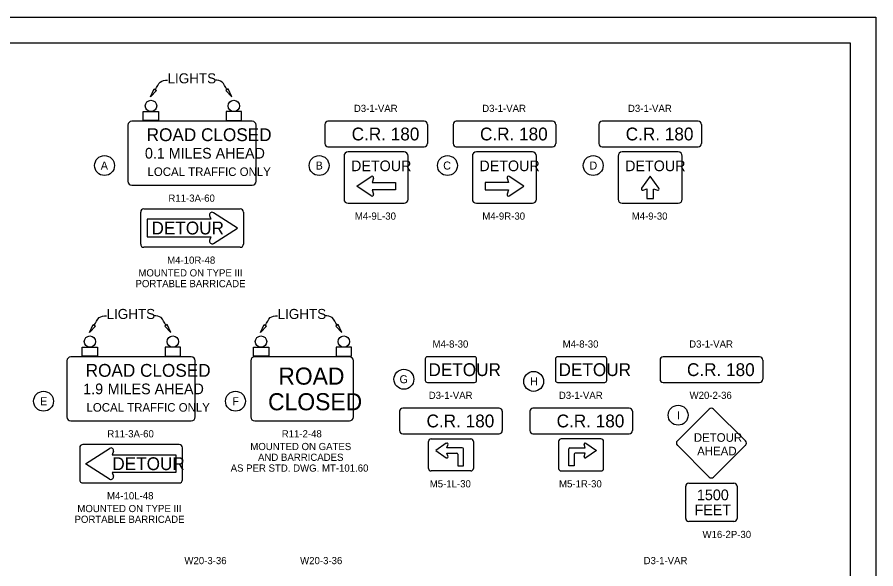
# Model space of a CAD drawing. Extents: x 1651.5 to 1685.5, y 1084.6 to 1106.6.
# Drawn here: x 1668.74 to 1685.46, y 1095.85 to 1106.6 of the extents above; entities that cross this region are included whole.
import ezdxf

# ---------------------------------------------------------------- set-up
doc = ezdxf.new("R2010")
doc.units = 0
for name, color, linetype in [('SC_Scratch1', 7, 'Continuous'), ('SH_Border', 7, 'Continuous'), ('SH_Text', 7, 'Continuous'), ('SN_P_Signs', 7, 'Continuous'), ('SN_P_Text', 7, 'Continuous')]:
    doc.layers.add(name, color=color, linetype=linetype)

msp = doc.modelspace()

# ---------------------------------------------------------------- linework, layer by layer
at = {"layer": 'SC_Scratch1'}
msp.add_lwpolyline([(1651.463, 1106.601), (1685.463, 1106.601), (1685.463, 1084.601), (1651.463, 1084.601)], close=True, dxfattribs=at)
at = {"layer": 'SH_Border'}
msp.add_lwpolyline([(1651.963, 1106.101), (1684.963, 1106.101), (1684.963, 1085.101), (1651.963, 1085.101)], close=True, dxfattribs=at)
at = {"layer": 'SH_Text'}
for centre in [(1670.438, 1103.708), (1674.618, 1103.708), (1677.118, 1103.708), (1679.958, 1103.708), (1676.27, 1099.542), (1678.797, 1099.5), (1669.25, 1099.114), (1672.989, 1099.114), (1681.612, 1098.841)]:
    msp.add_circle(centre, 0.194, dxfattribs=at)
at = {"layer": 'SN_P_Signs'}
for p, q in [((1675.353, 1103.307), (1675.634, 1103.497)), ((1678.603, 1103.307), (1678.322, 1103.497)), ((1681.068, 1103.503), (1680.9, 1103.264)), ((1681.236, 1103.264), (1681.068, 1103.503)), ((1675.677, 1103.465), (1675.65, 1103.38)), ((1675.65, 1103.38), (1676.103, 1103.38)), ((1676.103, 1103.38), (1676.103, 1103.234)), ((1678.306, 1103.38), (1677.853, 1103.38)), ((1677.853, 1103.38), (1677.853, 1103.234)), ((1678.279, 1103.465), (1678.306, 1103.38)), ((1675.634, 1103.116), (1675.353, 1103.307)), ((1676.103, 1103.234), (1675.65, 1103.234)), ((1675.65, 1103.234), (1675.677, 1103.149)), ((1677.853, 1103.234), (1678.306, 1103.234)), ((1678.306, 1103.234), (1678.279, 1103.149)), ((1678.322, 1103.116), (1678.603, 1103.307)), ((1680.928, 1103.227), (1681.005, 1103.251)), ((1681.005, 1103.251), (1681.005, 1103.25)), ((1681.005, 1103.25), (1681.005, 1103.066)), ((1681.131, 1103.251), (1681.208, 1103.227)), ((1681.005, 1103.066), (1681.131, 1103.066)), ((1672.507, 1102.661), (1671.268, 1102.661)), ((1671.268, 1102.661), (1671.268, 1102.318)), ((1672.485, 1102.731), (1672.507, 1102.661)), ((1673.028, 1102.489), (1672.559, 1102.788)), ((1672.559, 1102.191), (1673.028, 1102.489)), ((1671.268, 1102.318), (1672.507, 1102.318)), ((1672.507, 1102.318), (1672.485, 1102.248)), ((1676.749, 1097.804), (1676.749, 1098.329)), ((1676.799, 1098.379), (1677.574, 1098.379)), ((1677.624, 1098.329), (1677.624, 1097.804)), ((1679.284, 1098.329), (1679.284, 1097.804)), ((1680.109, 1098.379), (1679.334, 1098.379)), ((1680.159, 1097.804), (1680.159, 1098.329)), ((1670.069, 1097.896), (1670.537, 1098.194)), ((1670.612, 1098.137), (1670.59, 1098.068)), ((1677.094, 1098.293), (1676.89, 1098.153)), ((1676.89, 1098.153), (1677.094, 1098.013)), ((1677.109, 1098.208), (1677.13, 1098.278)), ((1677.406, 1098.208), (1677.109, 1098.208)), ((1677.406, 1098.208), (1677.406, 1098.208)), ((1677.429, 1097.856), (1677.429, 1098.184)), ((1679.48, 1097.856), (1679.48, 1098.184)), ((1679.503, 1098.208), (1679.8, 1098.208)), ((1679.503, 1098.208), (1679.503, 1098.208)), ((1679.8, 1098.208), (1679.779, 1098.278)), ((1679.815, 1098.293), (1680.019, 1098.153)), ((1680.019, 1098.153), (1679.815, 1098.013)), ((1670.59, 1098.068), (1671.829, 1098.068)), ((1671.829, 1098.068), (1671.829, 1097.724)), ((1677.13, 1098.028), (1677.109, 1098.098)), ((1677.109, 1098.098), (1677.304, 1098.098)), ((1677.32, 1098.083), (1677.32, 1097.856)), ((1679.589, 1098.083), (1679.589, 1097.856)), ((1679.8, 1098.098), (1679.605, 1098.098)), ((1679.779, 1098.028), (1679.8, 1098.098)), ((1670.537, 1097.597), (1670.069, 1097.896)), ((1677.32, 1097.856), (1677.429, 1097.856)), ((1677.32, 1097.856), (1677.429, 1097.856)), ((1679.589, 1097.856), (1679.48, 1097.856)), ((1671.829, 1097.724), (1670.59, 1097.724)), ((1670.59, 1097.724), (1670.612, 1097.654)), ((1677.574, 1097.754), (1676.799, 1097.754)), ((1679.334, 1097.754), (1680.109, 1097.754))]:
    msp.add_line(p, q, dxfattribs=at)
for points in [[(1671.451, 1105.172), (1671.333, 1105.049), (1671.404, 1105.203)], [(1672.8, 1105.172), (1672.918, 1105.049), (1672.847, 1105.203)], [(1671.193, 1104.587), (1671.193, 1104.759), (1671.492, 1104.759), (1671.492, 1104.587)], [(1673.105, 1104.587), (1673.105, 1104.759), (1672.806, 1104.759), (1672.806, 1104.587)], [(1670.263, 1100.578), (1670.145, 1100.455), (1670.216, 1100.61)], [(1671.612, 1100.578), (1671.729, 1100.455), (1671.658, 1100.61)], [(1673.594, 1100.578), (1673.477, 1100.455), (1673.548, 1100.61)], [(1674.944, 1100.578), (1675.061, 1100.455), (1674.99, 1100.61)], [(1670.005, 1099.993), (1670.005, 1100.165), (1670.304, 1100.165), (1670.304, 1099.993)], [(1671.917, 1099.993), (1671.917, 1100.165), (1671.618, 1100.165), (1671.618, 1099.993)], [(1673.337, 1099.993), (1673.337, 1100.165), (1673.636, 1100.165), (1673.636, 1099.993)], [(1675.249, 1099.993), (1675.249, 1100.165), (1674.95, 1100.165), (1674.95, 1099.993)]]:
    msp.add_lwpolyline(points, close=True, dxfattribs=at)
for points in [[(1670.893, 1104.495), (1670.893, 1103.401)], [(1673.314, 1104.573), (1670.971, 1104.573)], [(1673.393, 1103.401), (1673.393, 1104.495)], [(1674.728, 1104.511), (1674.728, 1104.136)], [(1676.666, 1104.573), (1674.791, 1104.573)], [(1676.728, 1104.511), (1676.728, 1104.136)], [(1677.228, 1104.511), (1677.228, 1104.136)], [(1679.166, 1104.573), (1677.291, 1104.573)], [(1679.228, 1104.511), (1679.228, 1104.136)], [(1680.068, 1104.511), (1680.068, 1104.136)], [(1682.005, 1104.573), (1680.13, 1104.573)], [(1682.068, 1104.511), (1682.068, 1104.136)], [(1674.791, 1104.073), (1676.666, 1104.073)], [(1677.291, 1104.073), (1679.166, 1104.073)], [(1680.13, 1104.073), (1682.005, 1104.073)], [(1675.103, 1103.893), (1675.103, 1103.053)], [(1676.273, 1103.973), (1675.183, 1103.973)], [(1676.353, 1103.053), (1676.353, 1103.893)], [(1677.603, 1103.893), (1677.603, 1103.053)], [(1678.773, 1103.973), (1677.683, 1103.973)], [(1678.853, 1103.053), (1678.853, 1103.893)], [(1680.443, 1103.893), (1680.443, 1103.053)], [(1681.613, 1103.973), (1680.523, 1103.973)], [(1681.693, 1103.053), (1681.693, 1103.893)], [(1670.971, 1103.323), (1673.314, 1103.323)], [(1681.131, 1103.066), (1681.131, 1103.25)], [(1671.205, 1102.864), (1673.08, 1102.864)], [(1675.183, 1102.973), (1676.273, 1102.973)], [(1677.683, 1102.973), (1678.773, 1102.973)], [(1680.523, 1102.973), (1681.613, 1102.973)], [(1671.143, 1102.177), (1671.143, 1102.802)], [(1673.143, 1102.802), (1673.143, 1102.177)], [(1673.08, 1102.114), (1671.205, 1102.114)], [(1672.126, 1099.979), (1669.782, 1099.979)], [(1675.208, 1099.979), (1673.364, 1099.979)], [(1677.647, 1099.979), (1676.727, 1099.979)], [(1680.182, 1099.979), (1679.262, 1099.979)], [(1683.197, 1099.979), (1681.322, 1099.979)], [(1669.704, 1099.901), (1669.704, 1098.808)], [(1672.204, 1098.808), (1672.204, 1099.901)], [(1673.286, 1099.901), (1673.286, 1098.808)], [(1675.286, 1098.808), (1675.286, 1099.901)], [(1676.687, 1099.939), (1676.687, 1099.519)], [(1677.687, 1099.519), (1677.687, 1099.939)], [(1679.222, 1099.939), (1679.222, 1099.519)], [(1680.222, 1099.519), (1680.222, 1099.939)], [(1681.26, 1099.917), (1681.26, 1099.542)], [(1683.26, 1099.917), (1683.26, 1099.542)], [(1676.727, 1099.479), (1677.647, 1099.479)], [(1679.262, 1099.479), (1680.182, 1099.479)], [(1681.322, 1099.479), (1683.197, 1099.479)], [(1678.124, 1098.979), (1676.249, 1098.979)], [(1680.659, 1098.979), (1678.784, 1098.979)], [(1676.187, 1098.917), (1676.187, 1098.542)], [(1678.187, 1098.917), (1678.187, 1098.542)], [(1678.722, 1098.917), (1678.722, 1098.542)], [(1680.722, 1098.917), (1680.722, 1098.542)], [(1681.597, 1098.342), (1682.216, 1098.961)], [(1682.304, 1098.961), (1682.923, 1098.342)], [(1669.782, 1098.729), (1672.126, 1098.729)], [(1673.364, 1098.729), (1675.208, 1098.729)], [(1676.249, 1098.479), (1678.124, 1098.479)], [(1678.784, 1098.479), (1680.659, 1098.479)], [(1669.954, 1098.208), (1669.954, 1097.583)], [(1671.892, 1098.271), (1670.017, 1098.271)], [(1671.954, 1097.583), (1671.954, 1098.208)], [(1682.216, 1097.635), (1681.597, 1098.254)], [(1682.923, 1098.254), (1682.304, 1097.635)], [(1670.017, 1097.521), (1671.892, 1097.521)], [(1681.822, 1097.517), (1682.697, 1097.517)], [(1681.76, 1096.83), (1681.76, 1097.455)], [(1682.76, 1097.455), (1682.76, 1096.83)], [(1682.697, 1096.767), (1681.822, 1096.767)]]:
    msp.add_lwpolyline(points, dxfattribs=at)
for centre in [(1671.343, 1104.87), (1672.956, 1104.87), (1670.154, 1100.276), (1671.768, 1100.276), (1673.486, 1100.276), (1675.099, 1100.276)]:
    msp.add_circle(centre, 0.111, dxfattribs=at)
for centre, radius, start, end in [((1670.971, 1104.495), 0.0781, 90, 180), ((1673.314, 1104.495), 0.0781, 0, 90), ((1674.791, 1104.511), 0.0625, 90, 180), ((1676.666, 1104.511), 0.0625, 0, 90), ((1677.291, 1104.511), 0.0625, 90, 180), ((1679.166, 1104.511), 0.0625, 0, 90), ((1680.13, 1104.511), 0.0625, 90, 180), ((1682.005, 1104.511), 0.0625, 0, 90), ((1674.791, 1104.136), 0.0625, 180, 270), ((1676.666, 1104.136), 0.0625, 270, 0), ((1677.291, 1104.136), 0.0625, 180, 270), ((1679.166, 1104.136), 0.0625, 270, 0), ((1680.13, 1104.136), 0.0625, 180, 270), ((1682.005, 1104.136), 0.0625, 270, 0), ((1675.183, 1103.893), 0.08, 90, 180), ((1676.273, 1103.893), 0.08, 0, 90), ((1677.683, 1103.893), 0.08, 90, 180), ((1678.773, 1103.893), 0.08, 0, 90), ((1680.523, 1103.893), 0.08, 90, 180), ((1681.613, 1103.893), 0.08, 0, 90), ((1675.65, 1103.473), 0.0286, 342.1992, 124.1969), ((1678.306, 1103.473), 0.0286, 55.8031, 197.8008), ((1670.971, 1103.401), 0.0781, 180, 270), ((1673.314, 1103.401), 0.0781, 270, 0), ((1675.65, 1103.14), 0.0286, 235.8031, 17.8008), ((1678.306, 1103.14), 0.0286, 162.1992, 304.1969), ((1680.92, 1103.25), 0.0246, 144.9207, 287.6378), ((1681.215, 1103.25), 0.0246, 252.3622, 35.0792), ((1675.183, 1103.053), 0.08, 180, 270), ((1676.273, 1103.053), 0.08, 270, 0), ((1677.683, 1103.053), 0.08, 180, 270), ((1678.773, 1103.053), 0.08, 270, 0), ((1680.523, 1103.053), 0.08, 180, 270), ((1681.613, 1103.053), 0.08, 270, 0), ((1671.205, 1102.802), 0.0625, 90, 180), ((1673.08, 1102.802), 0.0625, 0, 90), ((1672.532, 1102.746), 0.05, 57.4891, 197.8189), ((1671.205, 1102.177), 0.0625, 180, 270), ((1672.532, 1102.233), 0.05, 162.1811, 302.5109), ((1673.08, 1102.177), 0.0625, 270, 360), ((1669.782, 1099.901), 0.0781, 90, 180), ((1672.126, 1099.901), 0.0781, 0, 90), ((1673.364, 1099.901), 0.0783, 90, 180), ((1675.208, 1099.901), 0.0783, 0, 90), ((1676.727, 1099.939), 0.04, 90, 180), ((1677.647, 1099.939), 0.04, 0, 90), ((1679.262, 1099.939), 0.04, 90, 180), ((1680.182, 1099.939), 0.04, 0, 90), ((1681.322, 1099.917), 0.0625, 90, 180), ((1683.197, 1099.917), 0.0625, 0, 90), ((1676.727, 1099.519), 0.04, 180, 270), ((1677.647, 1099.519), 0.04, 270, 0), ((1679.262, 1099.519), 0.04, 180, 270), ((1680.182, 1099.519), 0.04, 270, 0), ((1681.322, 1099.542), 0.0625, 180, 270), ((1683.197, 1099.542), 0.0625, 270, 0), ((1676.249, 1098.917), 0.0625, 90, 180), ((1678.124, 1098.917), 0.0625, 0, 90), ((1678.784, 1098.917), 0.0625, 90, 180), ((1680.659, 1098.917), 0.0625, 0, 90), ((1682.26, 1098.917), 0.0625, 45, 135), ((1669.782, 1098.808), 0.0781, 180, 270), ((1672.126, 1098.808), 0.0781, 270, 0), ((1673.364, 1098.808), 0.0783, 180, 270), ((1675.208, 1098.808), 0.0783, 270, 0), ((1676.249, 1098.542), 0.0625, 180, 270), ((1678.124, 1098.542), 0.0625, 270, 0), ((1678.784, 1098.542), 0.0625, 180, 270), ((1680.659, 1098.542), 0.0625, 270, 0), ((1676.799, 1098.329), 0.05, 90, 180), ((1677.109, 1098.278), 0.0209, 0.0017, 134.9999), ((1677.574, 1098.329), 0.05, 0, 90), ((1679.334, 1098.329), 0.05, 90, 180), ((1679.8, 1098.278), 0.0209, 45.0001, 179.9983), ((1680.109, 1098.329), 0.05, 0, 90), ((1681.641, 1098.298), 0.0625, 135, 225), ((1682.879, 1098.298), 0.0625, 315, 45), ((1670.017, 1098.208), 0.0625, 90, 180), ((1670.564, 1098.152), 0.05, 342.1811, 122.5109), ((1671.892, 1098.208), 0.0625, 0, 90), ((1677.406, 1098.184), 0.0234, 0, 90), ((1679.503, 1098.184), 0.0234, 90, 180), ((1677.109, 1098.028), 0.0209, 225.0001, 0.0017), ((1677.304, 1098.083), 0.0156, 0, 90), ((1679.605, 1098.083), 0.0156, 90, 180), ((1679.8, 1098.028), 0.0209, 179.9983, 314.9999), ((1676.799, 1097.804), 0.05, 180, 270), ((1677.574, 1097.804), 0.05, 270, 360), ((1679.334, 1097.804), 0.05, 180, 270), ((1680.109, 1097.804), 0.05, 270, 0), ((1670.564, 1097.639), 0.05, 237.4891, 17.8189), ((1682.26, 1097.68), 0.0625, 225, 315), ((1670.017, 1097.583), 0.0625, 180, 270), ((1671.892, 1097.583), 0.0625, 270, 0), ((1681.822, 1097.455), 0.0625, 90, 180), ((1682.697, 1097.455), 0.0625, 0, 90), ((1681.822, 1096.83), 0.0625, 180, 270), ((1682.697, 1096.83), 0.0625, 270, 0)]:
    msp.add_arc(centre, radius, start, end, dxfattribs=at)
for points in [[(1671.428, 1105.188), (1671.464, 1105.241), (1671.501, 1105.367), (1671.616, 1105.37), (1671.662, 1105.372)], [(1672.823, 1105.188), (1672.787, 1105.241), (1672.75, 1105.367), (1672.635, 1105.37), (1672.589, 1105.372)], [(1670.239, 1100.594), (1670.275, 1100.647), (1670.312, 1100.774), (1670.428, 1100.776), (1670.474, 1100.778)], [(1671.635, 1100.594), (1671.599, 1100.647), (1671.562, 1100.774), (1671.447, 1100.776), (1671.401, 1100.778)], [(1673.571, 1100.594), (1673.607, 1100.647), (1673.644, 1100.774), (1673.76, 1100.776), (1673.805, 1100.778)], [(1674.967, 1100.594), (1674.931, 1100.647), (1674.894, 1100.774), (1674.779, 1100.776), (1674.733, 1100.778)]]:
    msp.add_open_spline(points, degree=3, dxfattribs=at)

# ---------------------------------------------------------------- texts
at = {"layer": 'SH_Text'}
for s, p in [('A', (1670.365, 1103.63)), ('B', (1674.551, 1103.63)), ('C', (1677.036, 1103.63)), ('D', (1679.885, 1103.63)), ('G', (1676.185, 1099.464)), ('H', (1678.727, 1099.422)), ('E', (1669.183, 1099.036)), ('F', (1672.928, 1099.036)), ('I', (1681.592, 1098.763))]:
    msp.add_text(s, height=0.156, dxfattribs=at).set_placement(p)
at = {"layer": 'SN_P_Signs'}
for s, height, p in [('LIGHTS', 0.196, (1671.665, 1105.31)), ('ROAD CLOSED', 0.25, (1671.259, 1104.184)), ('C.R. 180', 0.25, (1675.252, 1104.198)), ('C.R. 180', 0.25, (1677.752, 1104.198)), ('C.R. 180', 0.25, (1680.591, 1104.198)), ('0.1', 0.2083, (1671.225, 1103.844)), ('MILES AHEAD', 0.20833, (1671.689, 1103.844)), ('LOCAL TRAFFIC ONLY', 0.16667, (1671.275, 1103.504)), ('DETOUR', 0.2083, (1675.24, 1103.598)), ('DETOUR', 0.2083, (1677.74, 1103.598)), ('DETOUR', 0.2083, (1680.58, 1103.598)), ('DETOUR', 0.25, (1671.353, 1102.365)), ('LIGHTS', 0.196, (1670.477, 1100.717)), ('LIGHTS', 0.196, (1673.809, 1100.717)), ('ROAD CLOSED', 0.25, (1670.071, 1099.59)), ('DETOUR', 0.25, (1676.748, 1099.604)), ('DETOUR', 0.25, (1679.283, 1099.604)), ('C.R. 180', 0.25, (1681.784, 1099.604)), ('ROAD', 0.3333, (1673.824, 1099.437)), ('1.9', 0.2083, (1670.023, 1099.25)), ('MILES AHEAD', 0.20833, (1670.5, 1099.25)), ('CLOSED', 0.3333, (1673.624, 1098.937)), ('LOCAL TRAFFIC ONLY', 0.16667, (1670.087, 1098.91)), ('C.R. 180', 0.25, (1676.711, 1098.604)), ('C.R. 180', 0.25, (1679.245, 1098.604)), ('DETOUR', 0.1667, (1681.918, 1098.323)), ('AHEAD', 0.1667, (1681.983, 1098.059)), ('DETOUR', 0.25, (1670.59, 1097.771)), ('1500', 0.2083, (1681.979, 1097.184)), ('FEET', 0.2083, (1681.932, 1096.892))]:
    msp.add_text(s, height=height, dxfattribs=at).set_placement(p)
at = {"layer": 'SN_P_Text'}
for s, p in [('D3-1-VAR', (1675.295, 1104.753)), ('D3-1-VAR', (1677.795, 1104.753)), ('D3-1-VAR', (1680.635, 1104.753)), ('R11-3A-60', (1671.682, 1103.003)), ('M4-9L-30', (1675.314, 1102.653)), ('M4-9R-30', (1677.798, 1102.653)), ('M4-9-30', (1680.708, 1102.653)), ('M4-10R-48', (1671.658, 1101.794)), ('MOUNTED ON TYPE III', (1671.098, 1101.546)), ('PORTABLE BARRICADE', (1671.041, 1101.336)), ('M4-8-30', (1676.828, 1100.159)), ('M4-8-30', (1679.363, 1100.159)), ('D3-1-VAR', (1681.827, 1100.159)), ('D3-1-VAR', (1676.754, 1099.159)), ('D3-1-VAR', (1679.289, 1099.159)), ('W20-2-36', (1681.835, 1099.159)), ('R11-3A-60', (1670.493, 1098.409)), ('R11-2-48', (1673.89, 1098.409)), ('MOUNTED ON GATES', (1673.278, 1098.161)), ('AND BARRICADES ', (1673.428, 1097.951)), ('AS PER STD. DWG. MT-101.60', (1672.895, 1097.741)), ('M5-1L-30', (1676.773, 1097.434)), ('M5-1R-30', (1679.292, 1097.434)), ('M4-10L-48', (1670.486, 1097.201)), ('MOUNTED ON TYPE III', (1669.909, 1096.952)), ('PORTABLE BARRICADE', (1669.853, 1096.742)), ('W16-2P-30', (1682.087, 1096.447)), ('W20-3-36', (1671.994, 1095.937)), ('W20-3-36', (1674.248, 1095.937)), ('D3-1-VAR', (1680.94, 1095.937))]:
    msp.add_text(s, height=0.14, dxfattribs=at).set_placement(p)

doc.saveas('drawing.dxf')
